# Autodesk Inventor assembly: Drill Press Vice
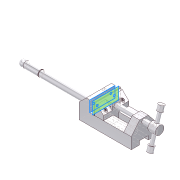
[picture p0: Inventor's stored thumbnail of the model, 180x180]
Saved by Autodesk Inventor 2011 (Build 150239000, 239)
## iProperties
Created: 2009-05
Part Number: Drill Press Vice
Document SubType Name: Assembly
Designer: Sham
Author: Sham
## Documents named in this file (9)
- C:\Inventor_2011\c10_inv_2010_05042010\Drill Press Vice\Drill Press Vice.iam
- C:\Inventor_2011\c10_inv_2010_05042010\Drill Press Vice\Base.ipt
- C:\Inventor_2011\c10_inv_2010_05042010\Drill Press Vice\Safety Handle.ipt
- C:\Inventor_2011\c10_inv_2010_05042010\Drill Press Vice\Jaw Face.ipt
- C:\Inventor_2011\c10_inv_2010_05042010\Drill Press Vice\Movable Jaw.ipt
- C:\Inventor_2011\c10_inv_2010_05042010\Drill Press Vice\Cap Screw.ipt
- C:\Inventor_2011\c10_inv_2010_05042010\Drill Press Vice\Clamp Screw Handle.ipt
- C:\Inventor_2011\c10_inv_2010_05042010\Drill Press Vice\Clamp Screw.ipt
- C:\Inventor_2011\c10_inv_2010_05042010\Drill Press Vice\Handle Stop.ipt
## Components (10 placed, 8 different names)
1. Base:1 — Mate:1, Mate:2, Mate:3, Flush:1
2. Safety Handle:1
3. Jaw Face:1 — Mate:1, Mate:4, Flush:1
4. Movable Jaw:1 — Mate:2, Mate:3, Mate:4, Insert:2, Insert:3, Insert:4
5. Cap Screw:1 — Insert:2
6. Cap Screw:2 — Insert:3
7. Clamp Screw:1 — Insert:4, Mate:6
8. Clamp Screw Handle:1 — Mate:6, Insert:5, Insert:6
9. Handle Stop:1 — Insert:6
10. Handle Stop:2 — Insert:5
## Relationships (11: Mate 5, Insert 5, Flush 1)
- Mate:1: Base:1 ↔ Jaw Face:1
- Mate:2: Base:1 ↔ Movable Jaw:1
- Mate:3: Base:1 ↔ Movable Jaw:1
- Mate:4: Jaw Face:1 ↔ Movable Jaw:1
- Insert:2: Movable Jaw:1 ↔ Cap Screw:1
- Insert:3: Movable Jaw:1 ↔ Cap Screw:2
- Insert:4: Movable Jaw:1 ↔ Clamp Screw:1
- Mate:6: Clamp Screw:1 ↔ Clamp Screw Handle:1
- Insert:5: Clamp Screw Handle:1 ↔ Handle Stop:2
- Insert:6: Clamp Screw Handle:1 ↔ Handle Stop:1
- Flush:1: Base:1 ↔ Jaw Face:1
